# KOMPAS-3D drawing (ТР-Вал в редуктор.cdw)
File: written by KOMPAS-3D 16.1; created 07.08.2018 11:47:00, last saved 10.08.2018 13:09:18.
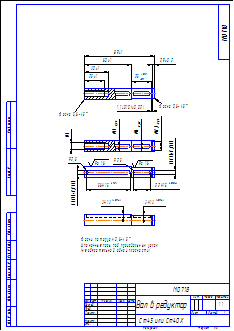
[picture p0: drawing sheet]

Sheet 1: A3, portrait

Title block, sheet 1: name: Вал в редуктор; designation: М0718; material: Ст45 или Ст40Х; scale: 1:1; sheets: 1; sheet format: A3; stored path: C:\Users\User\Desktop\Станки\Малый 0718\ТР-Вал в редуктор.cdw

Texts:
  User
  JS10( 0,02)
  JS10
  JS15
  JS9( 0,015)
  JS9
  Фаски по торцам 0,6 45
  Шпоночные пазы под произвольным углом
  (не обязательно в одной плоскости)
  Фаска 0,6 45
  Ra 1,6
Dimensions and other numbers on the sheet: 25±1; 30±1; 60±1; 89±1; 1,1; 2,9±0,2; 8; 14; 13; 12,4; 56; 22; 5; 2,5; 3; 1:1; 1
